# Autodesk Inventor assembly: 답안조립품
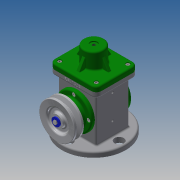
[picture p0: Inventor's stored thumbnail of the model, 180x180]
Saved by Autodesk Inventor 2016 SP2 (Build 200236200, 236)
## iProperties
Created: 2018-10
Part Number: 답안조립품
Document SubType Name: Assembly
Designer: Administrator
Author: Administrator
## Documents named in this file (18)
- \\d4\ATC마스터자격증시험\481007V1003 임관호\답안조립품.iam
- \\d4\ATC마스터자격증시험\481007V1003 임관호\E-링.ipt
- \\d4\ATC마스터자격증시험\481007V1003 임관호\볼트 M4 x 10.ipt
- \\d4\ATC마스터자격증시험\481007V1003 임관호\슬라이더.ipt
- \\d4\ATC마스터자격증시험\481007V1003 임관호\앞커버.ipt
- \\d4\ATC마스터자격증시험\481007V1003 임관호\오일 실 17 30 8.ipt
- \\d4\ATC마스터자격증시험\481007V1003 임관호\와셔 4x16.ipt
- \\d4\ATC마스터자격증시험\481007V1003 임관호\클레비스 핀 6 x 22.ipt
- 클레비스 핀 6 x 22.ipt
- \\d4\ATC마스터자격증시험\481007V1003 임관호\키 4 x 4 x 12.ipt
- \\d4\ATC마스터자격증시험\481007V1003 임관호\편심축.ipt
- \\d4\ATC마스터자격증시험\481007V1003 임관호\V-벨트풀리.ipt
- \\d4\ATC마스터자격증시험\481007V1003 임관호\덮개.ipt
- \\d4\ATC마스터자격증시험\481007V1003 임관호\뒤커버.ipt
- \\d4\ATC마스터자격증시험\481007V1003 임관호\링크.ipt
- \\d4\ATC마스터자격증시험\481007V1003 임관호\베어링 17 x 40 x 12.ipt
- \\d4\ATC마스터자격증시험\481007V1003 임관호\본체.ipt
- \\d4\ATC마스터자격증시험\481007V1003 임관호\볼트 M4 x 8.ipt
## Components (2 placed, 2 different names)
1. E-링:1
2. V-벨트풀리:1
## Component patterns: 구성요소 패턴 3:2 (2 elements)
